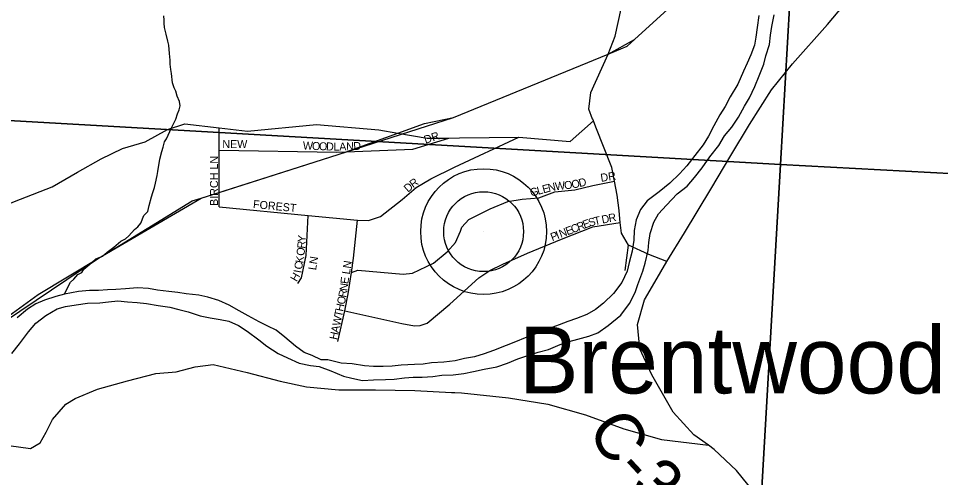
# Model space of a CAD drawing. Extents: x 0 to 34, y 0 to 22.
# Drawn here: x 4.825 to 5.915, y 16.609 to 17.152 of the extents above; entities that cross this region are included whole.
import ezdxf

# ---------------------------------------------------------------- set-up
doc = ezdxf.new("R2010")
doc.units = 0
for name, color, linetype in [('GM_P_State_Alignment', 7, 'Continuous'), ('GM_X_County_Road', 7, 'Continuous'), ('GM_X_County_Road_Text', 7, 'Continuous'), ('GM_X_Major_River', 7, 'Continuous'), ('GM_X_Minor_River', 7, 'Continuous'), ('GM_X_Section', 7, 'Continuous'), ('GM_X_Township_Road', 7, 'Continuous'), ('GM_X_Township_Subdivision', 7, 'Continuous'), ('GM_X_Township_Subdivision_Text', 7, 'Continuous'), ('GM_X_Unincorporated', 7, 'Continuous'), ('GM_X_Unincorporated_Location', 7, 'Continuous'), ('GM_X_Unincorporated_Text', 7, 'Continuous'), ('SH_Data', 7, 'Continuous')]:
    doc.layers.add(name, color=color, linetype=linetype)

msp = doc.modelspace()

# ---------------------------------------------------------------- linework, layer by layer
at = {"layer": 'GM_P_State_Alignment'}
msp.add_lwpolyline([(4.4093, 16.4472), (4.4624, 16.5517), (4.5028, 16.6273), (4.5501, 16.6611), (4.5937, 16.6923), (4.6421, 16.7261), (4.6758, 16.7352), (4.7521, 16.7559), (4.8479, 16.8253), (4.9193, 16.8683), (4.9287, 16.874), (5.0301, 16.936), (5.0406, 16.9393), (5.062, 16.9461), (5.2028, 16.9908), (5.2122, 16.9942), (5.2733, 17.0161), (5.3051, 17.0275), (5.3394, 17.0347), (5.5221, 17.1096), (5.5447, 17.1188), (5.5533, 17.1267), (5.6581, 17.2228)], dxfattribs=at)
at = {"layer": 'GM_X_County_Road'}
for points in [[(5.5038, 17.0326), (5.5037, 17.0328), (5.4991, 17.0444), (5.5018, 17.0641), (5.5221, 17.1096), (5.5306, 17.131), (5.5374, 17.1633), (5.5449, 17.2286), (5.543, 17.2548), (5.5217, 17.3217), (5.5119, 17.3479), (5.4906, 17.3763), (5.4504, 17.4245), (5.4186, 17.4507), (5.3757, 17.4833), (5.342, 17.5084), (5.3279, 17.5213), (5.3082, 17.5482), (5.2581, 17.6162), (5.2342, 17.6462), (5.221, 17.6617), (5.2123, 17.6727), (5.2113, 17.6825)], [(5.5775, 16.8401), (5.5775, 16.8401), (5.5917, 16.8644), (5.6126, 16.8982), (5.6436, 16.9499), (5.6671, 16.9898), (5.6894, 17.0263), (5.7152, 17.0673), (5.7402, 17.0981), (5.7815, 17.1445), (5.8068, 17.1749), (5.8224, 17.1954), (5.8246, 17.2189), (5.8121, 17.2554), (5.7704, 17.2971), (5.7687, 17.2983), (5.7687, 17.2984)], [(5.535, 16.9245), (5.535, 16.9246), (5.5329, 16.943), (5.5297, 16.9593), (5.5265, 16.9756), (5.5075, 17.0231), (5.5046, 17.0306), (5.5038, 17.0326)], [(5.5917, 16.8644), (5.5701, 16.8727), (5.5462, 16.8837), (5.5379, 16.8981), (5.5365, 16.9107), (5.535, 16.9245)], [(5.5424, 16.8539), (5.5462, 16.8837)], [(5.8127, 16.2622), (5.8074, 16.2897), (5.809, 16.2957), (5.8131, 16.3113), (5.8187, 16.3315), (5.8168, 16.3528), (5.7971, 16.3964), (5.7811, 16.4337), (5.7769, 16.4466), (5.7656, 16.4811), (5.7398, 16.5267), (5.7007, 16.5841), (5.6738, 16.6175), (5.6476, 16.6422), (5.6407, 16.6471), (5.6233, 16.6596), (5.599, 16.6862), (5.5736, 16.7303), (5.5596, 16.761), (5.5569, 16.7899), (5.5652, 16.8191), (5.5775, 16.8401)], [(4.8133, 16.6468), (4.839, 16.6432), (4.8504, 16.65), (4.8575, 16.6628), (4.865, 16.6778), (4.8807, 16.6956), (4.8917, 16.7024), (4.9181, 16.7134), (4.9535, 16.7233), (4.9873, 16.7321), (5.0111, 16.734), (5.0335, 16.7398), (5.0551, 16.7425), (5.0953, 16.7331), (5.1344, 16.7229), (5.1655, 16.7162), (5.2034, 16.7125), (5.247, 16.7126), (5.2936, 16.7119), (5.337, 16.7096)], [(5.337, 16.7096), (5.3407, 16.7094), (5.3486, 16.709), (5.4043, 16.7031), (5.4506, 16.6956), (5.4954, 16.6832), (5.5405, 16.6665), (5.5853, 16.6541), (5.6407, 16.6471)]]:
    msp.add_lwpolyline(points, dxfattribs=at)
at = {"layer": 'GM_X_Major_River'}
for points in [[(5.363, 16.7344), (5.3755, 16.7371), (5.3903, 16.7398), (5.4031, 16.7444), (5.4152, 16.7494), (5.4273, 16.7532), (5.4394, 16.7574), (5.4515, 16.7605), (5.4655, 16.7662), (5.4761, 16.7697), (5.4863, 16.7727), (5.4992, 16.7762), (5.5101, 16.78), (5.5222, 16.7888), (5.5373, 16.801), (5.5475, 16.8147), (5.5539, 16.8276), (5.5573, 16.8371), (5.5633, 16.853), (5.5659, 16.8625), (5.5693, 16.8774), (5.5704, 16.8869), (5.5719, 16.8975), (5.576, 16.9108), (5.5817, 16.9207), (5.5911, 16.931), (5.6039, 16.9443), (5.6156, 16.9534), (5.6243, 16.9637), (5.6334, 16.9751), (5.6424, 16.988), (5.653, 17.0017), (5.6597, 17.0128), (5.6684, 17.0234), (5.6763, 17.0352), (5.6835, 17.0481), (5.6891, 17.058), (5.6955, 17.0713), (5.7008, 17.0839), (5.7061, 17.0976), (5.7087, 17.1074), (5.7128, 17.1211), (5.7143, 17.1321), (5.7158, 17.1424), (5.7184, 17.1561)], [(5.7002, 17.1552), (5.6984, 17.1412), (5.6969, 17.1298), (5.695, 17.1203), (5.6909, 17.1089), (5.6864, 17.099), (5.6822, 17.0895), (5.6755, 17.0739), (5.6664, 17.0591), (5.6604, 17.0477), (5.654, 17.0378), (5.6472, 17.0249), (5.6408, 17.0127), (5.6344, 17.0025), (5.6246, 16.9899), (5.6152, 16.9777), (5.6065, 16.9682), (5.5952, 16.9572), (5.5823, 16.9469), (5.5684, 16.9362), (5.5604, 16.9259), (5.5552, 16.9138), (5.5529, 16.9012), (5.5526, 16.8895), (5.5504, 16.8766), (5.547, 16.8633), (5.5447, 16.853), (5.5384, 16.8397), (5.5285, 16.8264), (5.5168, 16.8153), (5.507, 16.8077), (5.4968, 16.8016), (5.4847, 16.797), (5.4745, 16.7936), (5.4643, 16.7894), (5.4511, 16.7848), (5.4386, 16.7798), (5.4238, 16.7741), (5.4125, 16.7695), (5.4015, 16.7653), (5.3864, 16.7591)], [(5.3864, 16.7591), (5.3754, 16.7553), (5.3641, 16.7519), (5.3524, 16.7496), (5.341, 16.7469), (5.3278, 16.7453), (5.313, 16.7445), (5.3032, 16.743), (5.293, 16.7426), (5.2774, 16.7418), (5.2668, 16.7406), (5.2559, 16.7402), (5.2445, 16.7401), (5.2339, 16.7409), (5.2195, 16.7435), (5.2063, 16.7442), (5.1907, 16.7483), (5.1828, 16.7483), (5.1722, 16.7532), (5.1627, 16.757), (5.1525, 16.7642), (5.1396, 16.7748), (5.1293, 16.7831), (5.1198, 16.788), (5.1092, 16.7929), (5.0963, 16.8001), (5.0857, 16.8061), (5.074, 16.8129), (5.0615, 16.8182), (5.0486, 16.8224), (5.038, 16.8246), (5.0232, 16.8261), (5.013, 16.8279), (5.0024, 16.8291), (4.9891, 16.8305), (4.9785, 16.8324), (4.9653, 16.8331), (4.9513, 16.832), (4.9399, 16.8312), (4.9301, 16.8308), (4.9195, 16.8303), (4.9089, 16.8303), (4.8956, 16.8291), (4.879, 16.8257), (4.8688, 16.823), (4.8555, 16.8188), (4.8453, 16.8142), (4.8355, 16.8081), (4.823, 16.7978)], [(4.8167, 16.7556), (4.8258, 16.7671), (4.8367, 16.7811), (4.8454, 16.7914), (4.8571, 16.8006), (4.8703, 16.8086), (4.8802, 16.8113), (4.893, 16.8132), (4.9063, 16.8151), (4.921, 16.8155), (4.9312, 16.8167), (4.9422, 16.8179), (4.9536, 16.8168), (4.9649, 16.816), (4.9763, 16.8146), (4.9899, 16.8123), (5.0036, 16.8105), (5.0145, 16.8078), (5.0255, 16.8048), (5.0396, 16.8003), (5.0513, 16.7977), (5.0634, 16.7958), (5.0736, 16.794), (5.085, 16.7887), (5.0952, 16.7822), (5.1089, 16.772), (5.1184, 16.7645), (5.1317, 16.7558), (5.1427, 16.7505), (5.1567, 16.7444), (5.1699, 16.7414), (5.1802, 16.7403), (5.1942, 16.7351), (5.2093, 16.729), (5.2188, 16.7264), (5.2317, 16.7238), (5.2446, 16.7246), (5.2589, 16.725), (5.2692, 16.7254), (5.2813, 16.727), (5.2915, 16.7277), (5.3021, 16.7278), (5.3146, 16.7286), (5.3256, 16.7301), (5.3388, 16.7305), (5.3513, 16.7321), (5.363, 16.7344)]]:
    msp.add_lwpolyline(points, dxfattribs=at)
at = {"layer": 'GM_X_Minor_River'}
msp.add_lwpolyline([(4.879, 16.8257), (4.8838, 16.8358), (4.8862, 16.8399), (4.89, 16.8437), (4.895, 16.8489), (4.8996, 16.8515), (4.902, 16.8553), (4.9116, 16.8631), (4.9162, 16.8676), (4.9242, 16.8708), (4.9296, 16.8753), (4.9373, 16.8813), (4.9457, 16.8884), (4.9511, 16.8913), (4.9553, 16.8947), (4.9619, 16.9022), (4.9657, 16.9055), (4.9696, 16.9096), (4.9731, 16.9187), (4.9778, 16.9236), (4.9794, 16.9308), (4.9822, 16.941), (4.9835, 16.9459), (4.9855, 16.9519), (4.9867, 16.9572), (4.9887, 16.966), (4.9896, 16.9709), (4.9917, 16.9853), (4.9942, 16.9944), (4.9958, 16.9997), (4.9974, 17.0057), (4.9997, 17.0095), (5.0037, 17.0182), (5.006, 17.0231), (5.0107, 17.0325), (5.0127, 17.0389), (5.0147, 17.0438), (5.0159, 17.0484), (5.0153, 17.0537), (5.0123, 17.0599), (5.0109, 17.0656), (5.0087, 17.0698), (5.0069, 17.0755), (5.0056, 17.0866), (5.0049, 17.0915), (5.0043, 17.0976), (5.004, 17.1026), (5.0034, 17.1102), (5.0024, 17.1201), (5.0014, 17.1247), (4.9992, 17.1331), (4.9975, 17.1411), (4.9972, 17.146), (4.9969, 17.1498), (4.9966, 17.1548)], dxfattribs=at)
at = {"layer": 'GM_X_Section'}
for points in [[(4.7124, 18.0487), (5.784, 17.9889), (5.726, 16.9791), (4.6537, 17.0401)], [(5.784, 17.9889), (6.8533, 17.9287), (6.7904, 16.9223), (5.726, 16.9791)], [(4.6537, 17.0401), (5.726, 16.9791), (5.677, 16.1322), (5.6584, 16.1262), (5.6277, 16.1155), (5.5967, 16.1068), (5.5364, 16.0882), (5.5129, 16.0795), (5.4883, 16.0696), (5.4618, 16.0586), (5.4391, 16.0502), (5.4232, 16.0453), (5.4004, 16.0385), (5.3732, 16.0309), (5.308, 16.0126), (5.2887, 16.0062), (5.2569, 15.9948), (5.2368, 15.9876), (4.5938, 16.0227)]]:
    msp.add_lwpolyline(points, close=True, dxfattribs=at)
msp.add_lwpolyline([(5.941, 16.2203), (5.8974, 16.2017), (5.863, 16.1896), (5.7789, 16.1638), (5.7652, 16.1596), (5.7364, 16.1497), (5.7118, 16.1406), (5.6963, 16.1368), (5.688, 16.1353), (5.677, 16.1322), (5.726, 16.9791), (6.7904, 16.9223)], dxfattribs=at)
at = {"layer": 'GM_X_Township_Road'}
for points in [[(4.7882, 16.9229), (4.8273, 16.9382), (4.8647, 16.9526), (4.8944, 16.9699), (4.9225, 16.9857), (4.9477, 16.9981), (4.9744, 17.0059), (5.0009, 17.0206), (5.0214, 17.027), (5.0621, 17.0225), (5.0957, 17.0184), (5.1771, 17.0262), (5.251, 17.0199), (5.2733, 17.0161), (5.3082, 17.0101), (5.3338, 17.0103), (5.3465, 17.0105)], [(5.3465, 17.0105), (5.4164, 17.0114), (5.4771, 17.0062), (5.5046, 17.0306)]]:
    msp.add_lwpolyline(points, dxfattribs=at)
at = {"layer": 'GM_X_Township_Subdivision'}
for points in [[(5.0621, 16.9913), (5.0621, 16.9959), (5.0621, 17.0225)], [(5.0621, 16.9959), (5.2012, 16.9938), (5.2122, 16.9942), (5.2911, 16.9971), (5.3338, 17.0103)], [(5.2256, 16.9131), (5.2385, 16.9128), (5.2529, 16.9177), (5.2786, 16.9376), (5.2949, 16.952), (5.3123, 16.9623), (5.3403, 16.9761), (5.4164, 17.0114)], [(5.062, 16.929), (5.062, 16.9461), (5.0621, 16.9913), (5.0621, 16.9913)], [(5.2184, 16.8514), (5.2261, 16.8542), (5.2796, 16.8494), (5.2906, 16.8506), (5.3156, 16.8624), (5.3318, 16.8758), (5.3417, 16.8868), (5.3473, 16.9001), (5.3492, 16.9051), (5.3575, 16.9142), (5.3825, 16.9268), (5.4033, 16.9352), (5.4204, 16.9383), (5.4401, 16.9395), (5.459, 16.9467), (5.4829, 16.9491), (5.5041, 16.9541), (5.5297, 16.9593)], [(5.062, 16.929), (5.1672, 16.9188), (5.2256, 16.9131)], [(5.1552, 16.8385), (5.1596, 16.8451), (5.165, 16.8714), (5.1672, 16.9188)], [(5.2105, 16.8062), (5.2782, 16.7913), (5.293, 16.7883), (5.2999, 16.7887), (5.3082, 16.7917), (5.3347, 16.8138), (5.3691, 16.8451), (5.3823, 16.8538), (5.3975, 16.8611), (5.4266, 16.8741), (5.4668, 16.8909), (5.5039, 16.9054), (5.5365, 16.9107)], [(5.2184, 16.8513), (5.2184, 16.8514), (5.2208, 16.8683), (5.2256, 16.9131)], [(5.2025, 16.7698), (5.2105, 16.8062), (5.2148, 16.8261), (5.2184, 16.8513)]]:
    msp.add_lwpolyline(points, dxfattribs=at)
at = {"layer": 'GM_X_Unincorporated'}
for radius in [0.0744, 0.0472]:
    msp.add_circle((5.3748, 16.8997), radius, dxfattribs=at)
at = {"layer": 'GM_X_Unincorporated_Location'}
msp.add_line((5.3748, 16.8997), (5.3748, 16.8997), dxfattribs=at)
at = {"layer": 'SH_Data'}
msp.add_lwpolyline([(4.3712, 16.3386), (4.4624, 16.5517), (4.5028, 16.6273), (4.6421, 16.7261), (4.7521, 16.7559), (4.9193, 16.8683), (5.0406, 16.9393), (5.2028, 16.9908), (5.3394, 17.0347), (5.5221, 17.1096), (5.5533, 17.1267), (5.6581, 17.2228), (5.7272, 17.3279), (5.7846, 17.4188), (6.0315, 17.5972)], dxfattribs=at)

# ---------------------------------------------------------------- texts
at = {"layer": 'GM_X_County_Road_Text'}
for s, rotation, p in [('C', 300.4786, (5.4968, 16.6675)), ('-', 312.9563, (5.5285, 16.6165)), ('3', 315.3643, (5.5462, 16.5976))]:
    msp.add_text(s, height=0.0568, rotation=rotation, dxfattribs=at).set_placement(p)
at = {"layer": 'GM_X_Township_Subdivision_Text'}
for s, rotation, p in [('DR', 18.4336, (5.3061, 17.0035)), ('NEW', 0, (5.0658, 16.9985)), ('W', 357.6456, (5.1609, 16.9969)), ('O', 357.6467, (5.1717, 16.9964)), ('O', 357.6453, (5.18, 16.9961)), ('D', 357.6467, (5.1883, 16.9958)), ('L', 359.8146, (5.1971, 16.9954)), ('A', 2.3357, (5.2042, 16.9954)), ('N', 2.4885, (5.2125, 16.9957)), ('D', 2.4897, (5.2209, 16.9961)), ('BIRCH LN', 90, (5.0607, 16.9301)), ('DR', 8.9729, (5.5138, 16.9585)), ('R', 36.3648, (5.2915, 16.9509)), ('W', 6.8268, (5.4598, 16.9485)), ('O', 6.0542, (5.4705, 16.9497)), ('O', 10.1586, (5.4796, 16.9507)), ('D', 13.6019, (5.4884, 16.9523)), ('D', 41.1222, (5.2854, 16.9456)), ('G', 15.1681, (5.4311, 16.941)), ('L', 15.1662, (5.4392, 16.9432)), ('E', 15.1662, (5.4456, 16.9449)), ('N', 13.0423, (5.452, 16.9466)), ('FOREST', 354.5078, (5.1018, 16.9277)), ('S', 16.6286, (5.5001, 16.9054)), ('T', 11.8719, (5.5063, 16.9073)), ('D', 11.308, (5.5153, 16.9091)), ('R', 11.3089, (5.5234, 16.9108)), ('N', 21.0515, (5.4661, 16.8923)), ('E', 21.0509, (5.4739, 16.8953)), ('C', 21.0565, (5.4801, 16.8977)), ('R', 21.0603, (5.4871, 16.9004)), ('E', 21.0613, (5.4941, 16.9031)), ('Y', 85.9238, (5.1642, 16.8869)), ('P', 21.0581, (5.456, 16.8884)), ('I', 21.0524, (5.4622, 16.8908)), ('R', 85.8803, (5.1637, 16.8794)), ('K', 79.858, (5.1613, 16.8618)), ('O', 84.1744, (5.1628, 16.8708)), ('C', 79.2515, (5.1598, 16.8543)), ('LN', 81.0322, (5.1766, 16.8537)), ('LN', 81.021, (5.2165, 16.8487)), ('H', 59.9908, (5.1537, 16.8398)), ('I', 79.3986, (5.1591, 16.8502)), ('N', 82.0218, (5.2136, 16.8291)), ('E', 82.251, (5.2147, 16.8374)), ('R', 79.5762, (5.2121, 16.8213)), ('O', 78.0449, (5.2104, 16.8129)), ('T', 78.029, (5.2072, 16.7982)), ('H', 78.0505, (5.2086, 16.8047)), ('W', 78.0434, (5.205, 16.7876)), ('A', 78.0449, (5.2033, 16.7795)), ('H', 78.0449, (5.2015, 16.7713))]:
    msp.add_text(s, height=0.00947, rotation=rotation, dxfattribs=at).set_placement(p)
at = {"layer": 'GM_X_Unincorporated_Text'}
msp.add_text('Brentwood', height=0.07898, rotation=0, dxfattribs=at).set_placement((5.4166, 16.7084))

doc.saveas('drawing.dxf')
